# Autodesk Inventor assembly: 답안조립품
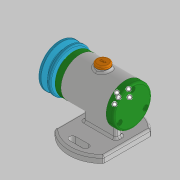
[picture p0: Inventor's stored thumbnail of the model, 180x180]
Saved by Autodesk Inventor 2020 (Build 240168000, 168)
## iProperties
Created: 2021-09
Part Number: 답안조립품
Document SubType Name: Assembly
Designer: Administrator
Author: Administrator
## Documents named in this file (13)
- C:\Users\Administrator\Desktop\710906V1019\답안조립품.iam
- C:\Users\Administrator\Desktop\710906V1019\본체.ipt
- C:\Users\Administrator\Desktop\710906V1019\축.ipt
- C:\Users\Administrator\Desktop\710906V1019\베어링 15x32x9.ipt
- C:\Users\Administrator\Desktop\710906V1019\앞커버.ipt
- C:\Users\Administrator\Desktop\710906V1019\뒤커버.ipt
- C:\Users\Administrator\Desktop\710906V1019\오일 실 15x25x7.ipt
- C:\Users\Administrator\Desktop\710906V1019\키 3x3.ipt
- C:\Users\Administrator\Desktop\710906V1019\V벨트풀리.ipt
- C:\Users\Administrator\Desktop\710906V1019\와셔 8x17.ipt
- C:\Users\Administrator\Desktop\710906V1019\스프링와셔 8.ipt
- C:\Users\Administrator\Desktop\710906V1019\너트 M8.ipt
- C:\Users\Administrator\Desktop\710906V1019\캡.ipt
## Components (1 placed, 1 different names)
1. V벨트풀리:1
